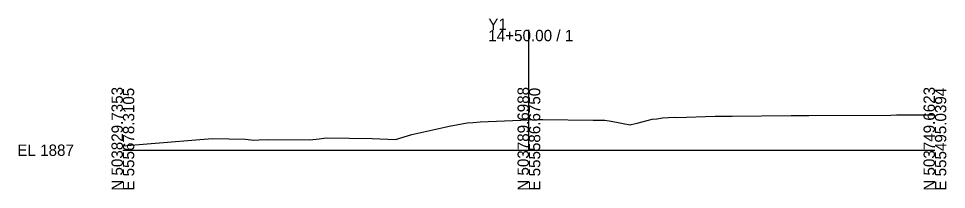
# Model space of a CAD drawing. Extents: x -26 to 203, y -10 to 5015.
# Drawn here: x -25.7 to 202.8, y 4490.3 to 4532.5 of the extents above; entities that cross this region are included whole.
import ezdxf

# ---------------------------------------------------------------- set-up
doc = ezdxf.new("R2010")
doc.units = 0
doc.layers.add('Exist Cross Section Cell', color=7, linetype='Continuous')
doc.layers.add('Exist XS Ground Line', color=7, linetype='Continuous')

msp = doc.modelspace()

# ---------------------------------------------------------------- linework, layer by layer
at = {"layer": 'Exist Cross Section Cell'}
for p, q in [((100, 4500), (100, 4529.69)), ((0, 4500), (100, 4500)), ((100, 4500), (200, 4500))]:
    msp.add_line(p, q, dxfattribs=at)
at = {"layer": 'Exist XS Ground Line'}
for p, q in [((80.33, 4505.92), (84.8, 4506.77)), ((84.8, 4506.77), (86.25, 4506.87)), ((86.25, 4506.87), (88.02, 4507.01)), ((88.02, 4507.01), (100, 4507.46)), ((100, 4507.46), (102.4, 4507.55)), ((102.4, 4507.55), (103.45, 4507.58)), ((103.45, 4507.58), (115.8, 4507.41)), ((115.8, 4507.41), (118.73, 4507.41)), ((118.73, 4507.41), (120.24, 4507.16)), ((120.24, 4507.16), (124.98, 4506.28)), ((126.63, 4506.65), (130.36, 4507.63)), ((130.36, 4507.63), (131.51, 4507.77)), ((131.51, 4507.77), (132.89, 4507.96)), ((132.89, 4507.96), (135.85, 4508.12)), ((135.85, 4508.12), (136.43, 4508.07)), ((136.43, 4508.07), (145.88, 4508.36)), ((145.88, 4508.36), (147.39, 4508.4)), ((147.39, 4508.4), (150.05, 4508.42)), ((150.05, 4508.42), (164.56, 4508.54)), ((164.56, 4508.54), (168.93, 4508.56)), ((168.93, 4508.56), (189.15, 4508.68)), ((189.15, 4508.68), (190.58, 4508.69)), ((190.58, 4508.69), (200, 4508.7)), ((71.19, 4503.84), (79.27, 4505.7)), ((79.27, 4505.7), (80.33, 4505.92)), ((124.98, 4506.28), (125.19, 4506.31)), ((125.19, 4506.31), (126.63, 4506.65)), ((6.01, 4501.59), (22.01, 4502.88)), ((22.01, 4502.88), (30.19, 4502.75)), ((30.19, 4502.75), (32.28, 4502.48)), ((32.28, 4502.48), (33.56, 4502.57)), ((33.56, 4502.57), (35.54, 4502.61)), ((35.54, 4502.61), (46.06, 4502.57)), ((46.06, 4502.57), (48.38, 4502.84)), ((48.38, 4502.84), (50.09, 4503.01)), ((50.09, 4503.01), (61.39, 4502.85)), ((61.39, 4502.85), (67.16, 4502.68)), ((67.16, 4502.68), (71.19, 4503.84)), ((0, 4501.09), (6.01, 4501.59))]:
    msp.add_line(p, q, dxfattribs=at)

# ---------------------------------------------------------------- texts
at = {"layer": 'Exist Cross Section Cell'}
for s, p in [('Y1', (90, 4529.69)), ('14+50.00 / 1', (90, 4526.89)), ('EL 1887', (-26, 4498.6))]:
    msp.add_text(s, height=2.8, dxfattribs=at).set_placement(p)
for s, p in [('N 503829.7353', (0, 4490)), ('E 555678.3105', (2.8, 4490)), ('N 503789.6988', (100, 4490)), ('E 555586.6750', (102.8, 4490)), ('N 503749.6623', (200, 4490)), ('E 555495.0394', (202.8, 4490))]:
    msp.add_text(s, height=2.8, rotation=90, dxfattribs=at).set_placement(p)

doc.saveas('drawing.dxf')
